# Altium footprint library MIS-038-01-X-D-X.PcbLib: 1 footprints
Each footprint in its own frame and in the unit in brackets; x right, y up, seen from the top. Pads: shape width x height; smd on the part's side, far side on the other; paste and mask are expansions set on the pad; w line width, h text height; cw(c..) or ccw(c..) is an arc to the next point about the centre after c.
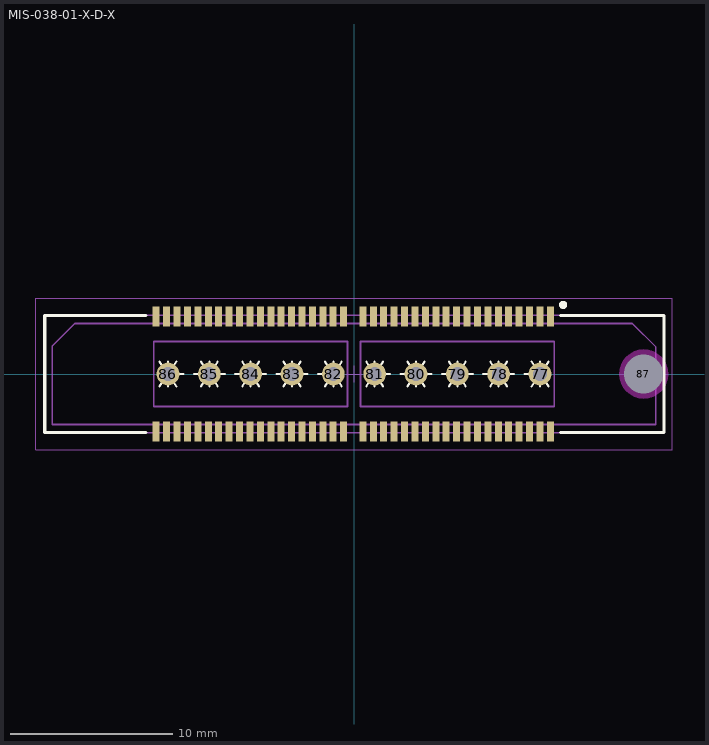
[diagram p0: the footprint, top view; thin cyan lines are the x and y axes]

## MIS-038-01-X-D-X [mm] "0.635mm pitch, mixed technology high speed socket"
height 3.63
pads (87):
  rect 0.43x1.25 smd mask+0: 1(12.065,3.53) 2(12.065,-3.53) 3(11.425,3.53) 4(11.425,-3.53) 5(10.785,3.53) 6(10.785,-3.53) 7(10.145,3.53) 8(10.145,-3.53) 9(9.505,3.53) 10(9.505,-3.53) 11(8.865,3.53) 12(8.865,-3.53) 13(8.225,3.53) 14(8.225,-3.53) 15(7.585,3.53) 16(7.585,-3.53) 17(6.945,3.53) 18(6.945,-3.53) 19(6.305,3.53) 20(6.305,-3.53) 21(5.665,3.53) 22(5.665,-3.53) 23(5.025,3.53) 24(5.025,-3.53) 25(4.385,3.53) 26(4.385,-3.53) 27(3.745,3.53) 28(3.745,-3.53) 29(3.105,3.53) 30(3.105,-3.53) 31(2.465,3.53) 32(2.465,-3.53) 33(1.825,3.53) 34(1.825,-3.53) 35(1.185,3.53) 36(1.185,-3.53) 37(0.545,3.53) 38(0.545,-3.53) 39(-0.635,3.53) 40(-0.635,-3.53) 41(-1.275,3.53) 42(-1.275,-3.53) 43(-1.915,3.53) 44(-1.915,-3.53) 45(-2.555,3.53) 46(-2.555,-3.53) 47(-3.195,3.53) 48(-3.195,-3.53) 49(-3.835,3.53) 50(-3.835,-3.53) 51(-4.475,3.53) 52(-4.475,-3.53) 53(-5.115,3.53) 54(-5.115,-3.53) 55(-5.755,3.53) 56(-5.755,-3.53) 57(-6.395,3.53) 58(-6.395,-3.53) 59(-7.035,3.53) 60(-7.035,-3.53) 61(-7.675,3.53) 62(-7.675,-3.53) 63(-8.315,3.53) 64(-8.315,-3.53) 65(-8.955,3.53) 66(-8.955,-3.53) 67(-9.595,3.53) 68(-9.595,-3.53) 69(-10.235,3.53) 70(-10.235,-3.53) 71(-10.875,3.53) 72(-10.875,-3.53) 73(-11.515,3.53) 74(-11.515,-3.53) 75(-12.155,3.53) 76(-12.155,-3.53)
  round 1.4 hole 0.85 mask+0: 77(11.43,0) 78(8.89,0) 79(6.35,0) 80(3.81,0) 81(1.27,0) 82(-1.27,0) 83(-3.81,0) 84(-6.35,0) 85(-8.89,0) 86(-11.43,0)
  round 1 hole 2.4 unplated mask+0: 87(17.78,0)
Top Overlay:
  circle w0.25: c12.85,4.25 r0.125
  lines w0.127: -11.944,-0.762 -10.916,0.762 ; -11.944,0.762 -10.916,-0.762 ; -11.43,-0.762 -11.43,0.762 ; -11.43,0 -10.478,0 ; -9.842,0 -7.938,0 ; -9.404,-0.762 -8.376,0.762 ; -9.404,0.762 -8.376,-0.762 ; -8.89,-0.762 -8.89,0.762 ; -7.302,0 -5.398,0 ; -6.864,-0.762 -5.836,0.762 ; -6.864,0.762 -5.836,-0.762 ; -6.35,-0.762 -6.35,0.762 ; -4.762,0 -2.858,0 ; -4.324,-0.762 -3.296,0.762 ; -4.324,0.762 -3.296,-0.762 ; -3.81,-0.762 -3.81,0.762 ; -2.222,0 -1.27,0 ; -1.784,-0.762 -0.756,0.762 ; -1.784,0.762 -0.756,-0.762 ; -1.27,-0.762 -1.27,0.762 ; 0.756,-0.762 1.784,0.762 ; 0.756,0.762 1.784,-0.762 ; 1.27,-0.762 1.27,0.762 ; 1.27,0 2.222,0 ; 2.858,0 4.762,0 ; 3.296,-0.762 4.324,0.762 ; 3.296,0.762 4.324,-0.762 ; 3.81,-0.762 3.81,0.762 ; 5.398,0 7.302,0 ; 5.836,-0.762 6.864,0.762 ; 5.836,0.762 6.864,-0.762 ; 6.35,-0.762 6.35,0.762 ; 7.938,0 9.842,0 ; 8.376,-0.762 9.404,0.762 ; 8.376,0.762 9.404,-0.762 ; 8.89,-0.762 8.89,0.762 ; 10.478,0 11.43,0 ; 10.916,-0.762 11.944,0.762 ; 10.916,0.762 11.944,-0.762 ; 11.43,-0.762 11.43,0.762
  lines w0.2: -12.8,-3.6 -19,-3.6 -19,3.6 -12.8,3.6 ; 12.7,-3.6 19.05,-3.6 19.05,3.6 12.7,3.6
Keep-Out Layer:
  pour cut-out: 19.307,0 19.278,0.294 19.193,0.577 19.053,0.837 18.866,1.066 18.637,1.253 18.377,1.393 18.094,1.478 17.8,1.507 17.506,1.478 17.223,1.393 16.963,1.253 16.734,1.066 16.547,0.837 16.407,0.577 16.322,0.294 16.293,0 16.322,-0.294 16.407,-0.577 16.547,-0.837 16.734,-1.066 16.963,-1.253 17.223,-1.393 17.506,-1.478 17.8,-1.507 18.094,-1.478 18.377,-1.393 18.637,-1.253 18.866,-1.066 19.053,-0.837 19.193,-0.577 19.278,-0.294
Mechanical 12:
  lines w0.001: -19.05,-3.6 -19.05,3.6 19.05,3.6 19.05,-3.6 -19.05,-3.6
Mechanical 13:
  lines w0.1: -19.05,-3.6 -19.05,3.6 19.05,3.6 19.05,-3.6 -19.05,-3.6 ; -18.55,-3.1 -18.55,1.71 -17.15,3.1 17.094,3.1 18.55,1.654 18.55,-3.1 -18.55,-3.1 ; -12.3,-2 -12.3,2 -0.4,2 -0.4,-2 -12.3,-2 ; 0.4,-2 0.4,2 12.3,2 12.3,-2 0.4,-2
  text ".Designator" at 0.254,0.254 h1.52
Mechanical 15:
  lines w0.05: -0.5,0 0.5,0 ; 0,-0.5 0,0.5 ; -19.55,-4.65 -19.55,4.65 19.55,4.65 19.55,-4.65 -19.55,-4.65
